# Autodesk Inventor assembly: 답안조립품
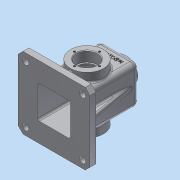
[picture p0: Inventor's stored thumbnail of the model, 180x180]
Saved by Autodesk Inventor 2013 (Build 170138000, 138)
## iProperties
Created: 2018-10
Part Number: 답안조립품
Document SubType Name: Assembly
Designer: Administrator
Author: Administrator
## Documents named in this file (2)
- C:\Users\Administrator\Desktop\인벤터시험\481013V1011\답안조립품.iam
- C:\Users\Administrator\Desktop\인벤터시험\481013V1011\본체.ipt
